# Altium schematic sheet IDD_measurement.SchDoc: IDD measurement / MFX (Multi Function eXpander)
size A4; Date: 01-DEC-2013; Author: A.B; CompanyName: STMicroelectronics; Organization: Microcontrollers Division; Address1: 12, Rue Jules HOROWITZ; Address2: 38019 Grenoble; Address3: FRANCE; DocumentNumber: MB1184; Revision: C-01; SheetNumber: 4; SheetTotal: 10; Project: STM32L476G-DISCO
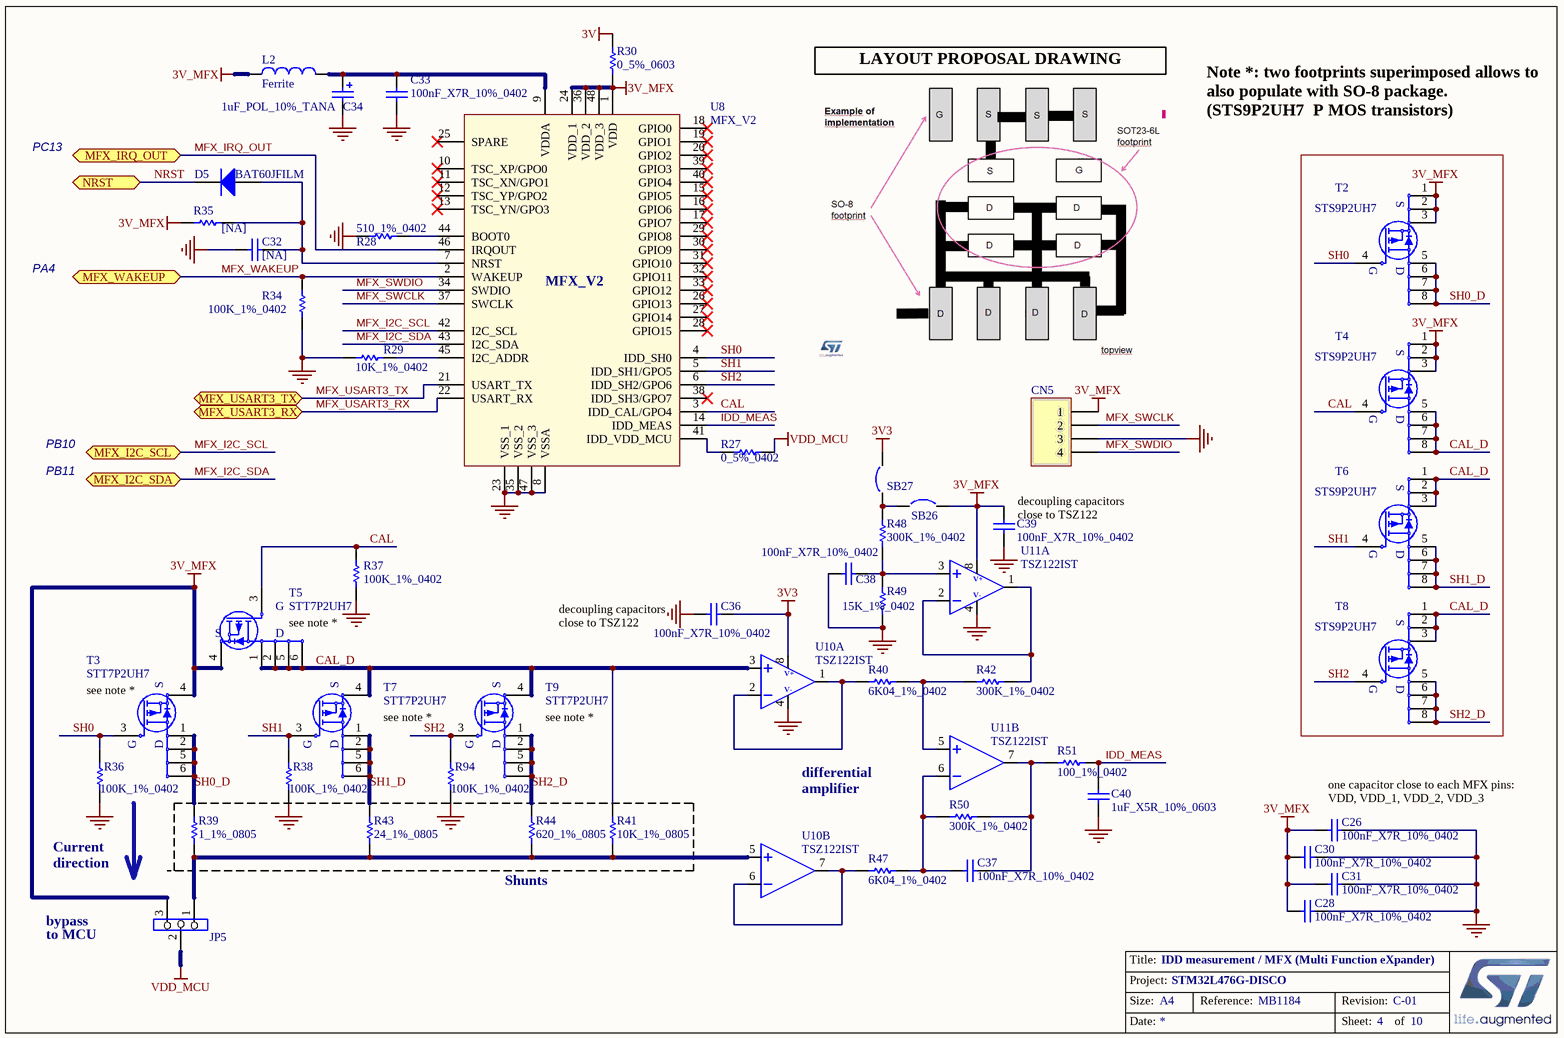
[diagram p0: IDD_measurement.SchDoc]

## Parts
C26  100nF_X7R_10%_0402  [0402C]
C28  100nF_X7R_10%_0402  [0402C]
C30  100nF_X7R_10%_0402  [0402C]
C31  100nF_X7R_10%_0402  [0402C]
C32  [NA]  [0402C]
C33  100nF_X7R_10%_0402  [0402C]
C34  1uF_POL_10%_TANA  [TAN-A]
C36  100nF_X7R_10%_0402  [0402C]
C37  100nF_X7R_10%_0402  [0402C]
C38  100nF_X7R_10%_0402  [0402C]
C39  100nF_X7R_10%_0402  [0402C]
C40  1uF_X5R_10%_0603  [0603C]
CN5  Header 4  [Header 4]  (value not drawn)
D5  BAT60JFILM  [SOD323/A]
JP5  Jumper 3 pins  [SIP3]  (value not drawn)
L2  Ferrite  [0603L]
R27  0_5%_0402  [0402R]
R28  510_1%_0402  [0402R]
R29  10K_1%_0402  [0402R]
R30  0_5%_0603  [0603R-GS]
R34  100K_1%_0402  [0402R]
R35  [NA]  [0402R]
R36  100K_1%_0402  [0402R]
R37  100K_1%_0402  [0402R]
R38  100K_1%_0402  [0402R]
R39  1_1%_0805  [0805R]
R40  6K04_1%_0402  [0402R]
R41  10K_1%_0805  [0805R]
R42  300K_1%_0402  [0402R]
R43  24_1%_0805  [0805R]
R44  620_1%_0805  [0805R]
R47  6K04_1%_0402  [0402R]
R48  300K_1%_0402  [0402R]
R49  15K_1%_0402  [0402R]
R50  300K_1%_0402  [0402R]
R51  100_1%_0402  [0402R]
R94  100K_1%_0402  [0402R]
SB26  Circuit Breaker  [JP2_SMD]  (value not drawn)
SB27  Circuit Breaker  [JP2_SMD]  (value not drawn)
T2  STS9P2UH7  [SO8]
T3  STT7P2UH7  [SOT23-6L]
T4  STS9P2UH7  [SO8]
T5  STT7P2UH7  [SOT23-6L]
T6  STS9P2UH7  [SO8]
T7  STT7P2UH7  [SOT23-6L]
T8  STS9P2UH7  [SO8]
T9  STT7P2UH7  [SOT23-6L]
U8  MFX_V2  [QFP48 7X7]
U10  TSZ122IST  [miniSO8]  (parts A,B of 2)
U11  TSZ122IST  [miniSO8]  (parts A,B of 2)

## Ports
MFX_I2C_SCL, MFX_I2C_SDA, MFX_IRQ_OUT, MFX_USART3_RX, MFX_USART3_TX, MFX_WAKEUP, NRST

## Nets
3V: R30.2
3V3: C36.2 SB27.2 U10.8
3V_MFX: C26.1 C28.1 C30.1 C31.1 C39.2 CN5.1 JP5.3 L2.1 R30.1 R35.1 SB26.2 T2.1(S) T2.2(S) T2.3(S) T3.4(S) T4.1(S) T4.2(S) T4.3(S) T5.4(S) U8.1(VDD) U8.24(VDD_1) U8.36(VDD_2) U8.48(VDD_3) U11.8
GND: C26.2 C28.2 C30.2 C31.2 C32.1 C33.1 C34.2 C36.1 C38.1 C39.1 C40.1 CN5.3 R28.1 R29.1 R34.1 R36.1 R37.1 R38.1 R49.1 R94.1 U8.8(VSSA) U8.23(VSS_1) U8.35(VSS_2) U8.47(VSS_3) U10.4 U11.4
VDD_MCU: JP5.2 R27.2
CAL: R37.2 T4.4(G) T5.3(G) U8.3(IDD_CAL/GPO4)
CAL_D: R41.2 T4.5(D) T4.6(D) T4.7(D) T4.8(D) T5.1(S) T5.2(S) T5.5(D) T5.6(D) T6.1(S) T6.2(S) T6.3(S) T7.4(S) T8.1(S) T8.2(S) T8.3(S) T9.4(S) U10.3
IDD_MEAS: C40.2 R51.2 U8.14(IDD_MEAS)
MFX_I2C_SCL: U8.42(I2C_SCL) ; port MFX_I2C_SCL
MFX_I2C_SDA: U8.43(I2C_SDA) ; port MFX_I2C_SDA
MFX_IRQ_OUT: U8.46(IRQOUT) ; port MFX_IRQ_OUT
MFX_SWCLK: CN5.2 U8.37(SWCLK)
MFX_SWDIO: CN5.4 U8.34(SWDIO)
MFX_USART3_RX: U8.22(USART_RX) ; port MFX_USART3_RX
MFX_USART3_TX: U8.21(USART_TX) ; port MFX_USART3_TX
MFX_WAKEUP: R34.2 U8.2(WAKEUP) ; port MFX_WAKEUP
NRST: D5.2(K) ; port NRST
SH0: R36.2 T2.4(G) T3.3(G) U8.4(IDD_SH0)
SH0_D: R39.2 T2.5(D) T2.6(D) T2.7(D) T2.8(D) T3.1(S) T3.2(S) T3.5(D) T3.6(D)
SH1: R38.2 T6.4(G) T7.3(G) U8.5(IDD_SH1/GPO5)
SH1_D: R43.2 T6.5(D) T6.6(D) T6.7(D) T6.8(D) T7.1(S) T7.2(S) T7.5(D) T7.6(D)
SH2: R94.2 T8.4(G) T9.3(G) U8.6(IDD_SH2/GPO6)
SH2_D: R44.2 T8.5(D) T8.6(D) T8.7(D) T8.8(D) T9.1(S) T9.2(S) T9.5(D) T9.6(D)
NetC32_2: C32.2 D5.1(A) R35.2 U8.7(NRST)
NetC33_2: C33.2 C34.1 L2.2 U8.9(VDDA)
NetC37_1: C37.1 R47.2 R50.1 U11.6
NetC37_2: C37.2 R50.2 R51.1 U11.7
NetC38_2: C38.2 R48.1 R49.2 U11.3
NetJP5_1: JP5.1 R39.1 R41.1 R43.1 R44.1 U10.5
NetR27_1: R27.1 U8.41(IDD_VDD_MCU)
NetR28_2: R28.2 U8.44(BOOT0)
NetR29_2: R29.2 U8.45(I2C_ADDR)
NetR40_1: R40.1 U10.1 U10.2
NetR40_2: R40.2 R42.1 U11.5
NetR42_2: R42.2 U11.1 U11.2
NetR47_1: R47.1 U10.6 U10.7
NetR48_2: R48.2 SB26.1 SB27.1

Not connected (* = marked no-connect by the designer): U8 10(TSC_XP/GPO0)* 11(TSC_XN/GPO1)* 12(TSC_YP/GPO2)* 13(TSC_YN/GPO3)* 15(GPIO5)* 16(GPIO6)* 17(GPIO7)* 18(GPIO0)* 19(GPIO1)* 20(GPIO2)* 25(SPARE)* 26(GPIO13)* 27(GPIO14)* 28(GPIO15)* 29(GPIO8)* 30(GPIO9)* 31(GPIO10)* 32(GPIO11)* 33(GPIO12)* 38(IDD_SH3/GPO7)* 39(GPIO3)* 40(GPIO4)*

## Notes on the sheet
- LAYOUT PROPOSAL DRAWING
- PC13
- Note *: two footprints superimposed allows to also populate with SO-8 package.
  (STS9P2UH7  P MOS transistors)
- PA4
- PB10
- PB11
- (near C39) decoupling capacitors
  close to TSZ122
- (near T5) see note *
- (near C36) decoupling capacitors
  close to TSZ122
- (near T3) see note *
- see note *
- (near T9) see note *
- differential
  amplifier
- (near C26) one capacitor close to each MFX pins: VDD, VDD_1, VDD_2, VDD_3
- Current direction
- Shunts
- to MCU
- bypass

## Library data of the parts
C26 C28 C30 C31 C33 C36-C39 = Cap_100nF_X7R_10%_0402: Capacitor,100nF,16V,X7R,10%,0402,YAGEO; Manuf_Part_1: CC0402KRX7R7BB104
C32 = Cap_NA_0402: Capacitor,NA,0402; Fitted: NO
C34 = Cap_1uF_POL_10%_TANA: Polarized Capacitor,1uF,16V,10%,typeA,AVX; Manuf_Part_1: TAJA105K016R
C40 = Cap_1uF_X5R_10%_0603: Capacitor,1uF,16V,X5R,10%,0603,YAGEO; Manuf_Part_1: CC0603KRX5R7BB105
CN5 = Header 4: Header, 4-Pin; Fitted: NO
D5 = BAT60JFILM: Manuf_1: STM; Provided: ST; ECCN_US/EU: EAR99/NEC; Ref St: 9151097
JP5 = Jumper3
L2 = BEAD_600R_350MA_0603: Bead,600R,350mA,0603,FCM1608KF-601T03,Tai-tech; Manuf_2: TDK; Manuf_Part_2: MPZ1608S300A; Value: 100uH; Comment_1: bead,30R,5A,0603,MPZ1608S300A,TDK; Ordered by: Subcon
R27 = Res_0_5%_0402: Resistor,0,0402,5%,YAGEO; Manuf_Part_1: RC0402JR-070RL; Value: 0; Order: 2363467
R28 = Res_510_1%_0402: Resistor,510,0402,1%,YAGEO; Manuf_Part_1: RC0402FR-07510L; Value: 510
R29 = Res_10K_1%_0402: Resistor,10K,0402,1%,YAGEO; Manuf_Part_1: RC0402FR-0710KL
R30 = Res_0_5%_0603: Resistor,0,0603,5%,YAGEO; Manuf_Part_1: RC0603JR-070RL; Value: 0; Order: 2363481
R34 R36-R38 R94 = Res_100K_1%_0402: Resistor,100K,0402,1%,YAGEO; Manuf_Part_1: RT0402FRE07100KL
R35 = Res_NA_0402: Resistor,[NA],0402; Fitted: NO
R39 = Res_1_1%_0805: Resistor,1,0805,1%,YAGEO; Manuf_Part_1: RC0805FR-071RL; Value: 1
R40 R47 = Res_6K04_1%_0402: Resistor,6K04,0402,1%,YAGEO; Manuf_Part_1: RC0402FR-076K04L
R41 = Res_10K_1%_0805: Resistor,10K,0805,1%,YAGEO; Manuf_Part_1: RC0805FR-0710KL
R42 R48 R50 = Res_300K_1%_0402: Resistor,300K,0402,1%,YAGEO; Manuf_Part_1: RC0402FR-07300KL
R43 = Res_24_1%_0805: Resistor,24,0805,1%,YAGEO; Manuf_Part_1: RC0805FR-0724RL; Value: 24
R44 = Res_620_1%_0805: Resistor,620,0805,1%,YAGEO; Manuf_Part_1: RC0805FR-07620RL; Value: 620
R49 = Res_15K_1%_0402: Resistor,15K,0402,1%,YAGEO; Manuf_Part_1: RC0402FR-0715KL
R51 = Res_100_1%_0402: Resistor,100,0402,1%,YAGEO; Manuf_Part_1: RC0402FR-07100RL; Value: 100; Order: 9239111
SB26 = Circuit Breaker: Solder: YES
SB27 = Circuit Breaker: Solder: NO
T2 = STS7P2UH7: STripFET VII Power MOSFET, P-CHANNEL 20V - 0.023 - 7A - SO-8; Manuf_1: STM; Provided: ST; Ref St: xxxxxxxx; ECCN_US/EU: EAR99/NEC; Fitted: NO; Comments: exclusive with T9
T3 = STT7P2UH7: STripFET VII DeepGATE Power MOSFET, P-CHANNEL 20 V, 0.0146, 7 A - SOT23-6L; Manuf_1: STM; Provided: ST; Ref St: xxxxxxxx; ECCN_US/EU: EAR99/NEC; Comments: exclusive with T8
T4 = STS7P2UH7: STripFET VII Power MOSFET, P-CHANNEL 20V - 0.023 - 7A - SO-8; Manuf_1: STM; Provided: ST; Ref St: xxxxxxxx; ECCN_US/EU: EAR99/NEC; Fitted: NO; Comments: exclusive with T5
T5 = STT7P2UH7: STripFET VII DeepGATE Power MOSFET, P-CHANNEL 20 V, 0.0146, 7 A - SOT23-6L; Manuf_1: STM; Provided: ST; Ref St: xxxxxxxx; ECCN_US/EU: EAR99/NEC; Comments: exclusive with T2
T6 = STS7P2UH7: STripFET VII Power MOSFET, P-CHANNEL 20V - 0.023 - 7A - SO-8; Manuf_1: STM; Provided: ST; Ref St: xxxxxxxx; ECCN_US/EU: EAR99/NEC; Fitted: NO; Comments: exclusive with T6
T7 = STT7P2UH7: STripFET VII DeepGATE Power MOSFET, P-CHANNEL 20 V, 0.0146, 7 A - SOT23-6L; Manuf_1: STM; Provided: ST; Ref St: xxxxxxxx; ECCN_US/EU: EAR99/NEC; Comments: exclusive with T3
T8 = STS7P2UH7: STripFET VII Power MOSFET, P-CHANNEL 20V - 0.023 - 7A - SO-8; Manuf_1: STM; Provided: ST; Ref St: xxxxxxxx; ECCN_US/EU: EAR99/NEC; Fitted: NO; Comments: exclusive with T7
T9 = STT7P2UH7: STripFET VII DeepGATE Power MOSFET, P-CHANNEL 20 V, 0.0146, 7 A - SOT23-6L; Manuf_1: STM; Provided: ST; Ref St: xxxxxxxx; ECCN_US/EU: EAR99/NEC; Comments: exclusive with T4
U8 = MFX_V2: MultiFunction eXpander (STM32L152CCT6); Manuf_1: STM; ECCN_US/EU: 3A991A2/NEC; Provided: ST
U10 U11 = TSZ122IST: Very high accuracy (5 µV) zero drift 5 V dual OpAmp; Manuf_1: STM; ECCN_US/EU: EAR99/NEC; Provided: ST; Ref St: xxxxxxxxx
